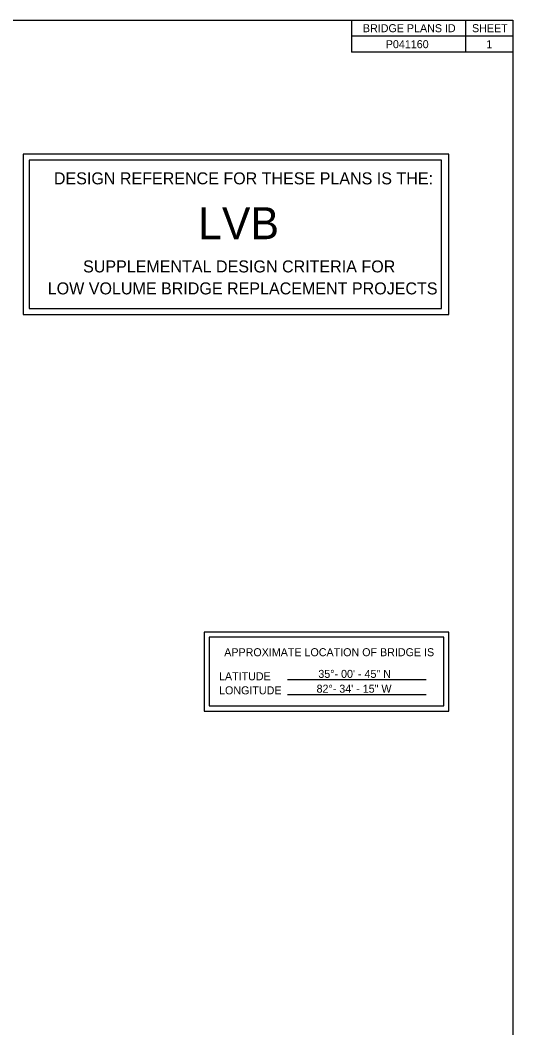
# Model space of a CAD drawing. Extents: x -4.82 to 4.15, y -0.44 to 2.32.
# Drawn here: x 2.15 to 2.792, y 0.48 to 1.792 of the extents above; entities that cross this region are included whole.
import ezdxf

# ---------------------------------------------------------------- set-up
doc = ezdxf.new("R2010")
doc.units = 0
for name, color, linetype in [('BR_AUTO DIMENSION', 7, 'Continuous'), ('BR_BORDER LINES', 7, 'Continuous'), ('BR_DETAILS', 7, 'Continuous'), ('Default', 7, 'Continuous')]:
    doc.layers.add(name, color=color, linetype=linetype)

msp = doc.modelspace()

# ---------------------------------------------------------------- linework, layer by layer
at = {"layer": 'BR_AUTO DIMENSION'}
for points in [[(2.1545, 1.4087), (2.7083, 1.4087), (2.7083, 1.6171), (2.1545, 1.6171)], [(2.1623, 1.4165), (2.6989, 1.4165), (2.6989, 1.6093), (2.1623, 1.6093)]]:
    msp.add_lwpolyline(points, close=True, dxfattribs=at)
at = {"layer": 'BR_BORDER LINES'}
for p, q in [((2.5815, 1.7917), (2.5815, 1.75)), ((2.73, 1.7917), (2.73, 1.75)), ((2.7917, 1.7708), (2.5815, 1.7708)), ((2.7917, 1.75), (2.5815, 1.75))]:
    msp.add_line(p, q, dxfattribs=at)
for points in [[(0.1667, 1.7917), (2.7917, 1.7917), (2.7917, 0.0417), (0.1667, 0.0417)], [(2.7084, 0.9954), (2.39, 0.9954), (2.39, 0.8927), (2.7084, 0.8927)], [(2.7017, 0.9887), (2.3966, 0.9887), (2.3966, 0.8994), (2.7017, 0.8994)]]:
    msp.add_lwpolyline(points, close=True, dxfattribs=at)
at = {"layer": 'BR_DETAILS'}
for p, q in [((2.4985, 0.9337), (2.6787, 0.9337)), ((2.4985, 0.9144), (2.6787, 0.9144))]:
    msp.add_line(p, q, dxfattribs=at)

# ---------------------------------------------------------------- texts
at = {"layer": 'Default'}
for s, height, p in [('BRIDGE PLANS ID', 0.010417, (2.5965, 1.776)), ('SHEET', 0.01042, (2.7385, 1.776)), ('P041160', 0.01042, (2.6263, 1.7552)), ('1', 0.0104, (2.7572, 1.7552)), ('DESIGN REFERENCE FOR THESE PLANS IS THE:', 0.015625, (2.1943, 1.578)), ('LVB', 0.04167, (2.382, 1.5066)), ('SUPPLEMENTAL DESIGN CRITERIA FOR', 0.015625, (2.2323, 1.4634)), ('LOW VOLUME BRIDGE REPLACEMENT PROJECTS', 0.015625, (2.1863, 1.4348)), ('APPROXIMATE LOCATION OF BRIDGE IS', 0.010417, (2.416, 0.964)), ('35°- 00\' - 45" N', 0.010417, (2.5385, 0.9358)), ('LATITUDE', 0.01042, (2.4092, 0.9327)), ('LONGITUDE', 0.01042, (2.4093, 0.9144)), ('82°- 34\' - 15" W', 0.010417, (2.5362, 0.9165))]:
    msp.add_text(s, height=height, dxfattribs=at).set_placement(p)

doc.saveas('drawing.dxf')
